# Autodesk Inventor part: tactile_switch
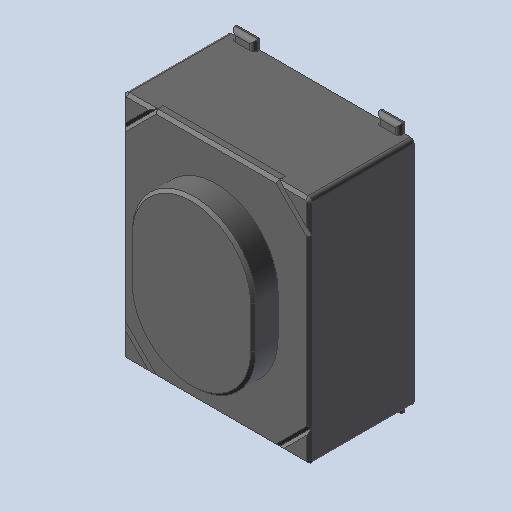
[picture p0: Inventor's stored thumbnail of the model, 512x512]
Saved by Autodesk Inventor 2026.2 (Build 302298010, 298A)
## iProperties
Created: 2026-10
Part Number: tactile_switch
Material: Générique
Document SubType Name: Modeling
Designer: mel
Density: 1 g/cm^3
Appearance: Par défaut
Author: mel
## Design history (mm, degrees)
feature "Base1"
feature "Base2"
feature "Base3"
feature "Base4"
feature "Base5"
feature "Base6"
feature "Base7"
node "Solide1"
node "Solide2"
node "Solide3"
node "Solide4"
node "Solide5"
node "Solide6"
node "Solide7"
